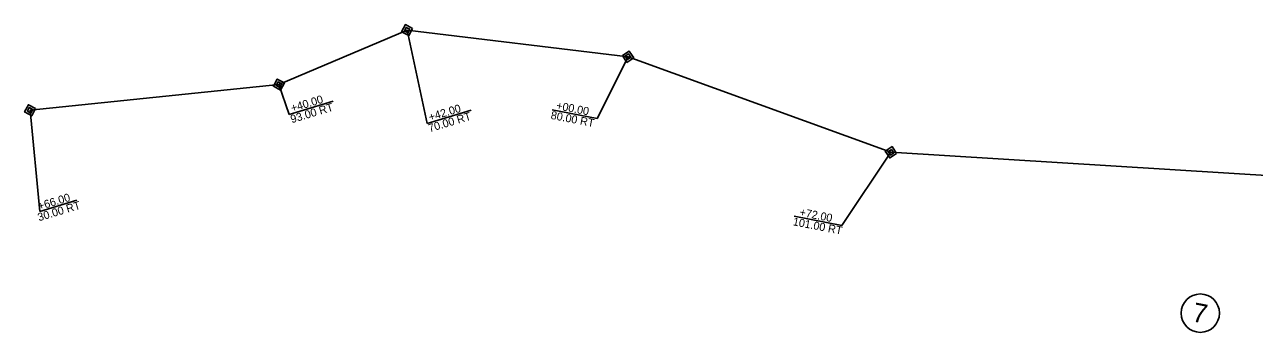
# Model space of a CAD drawing. Extents: x 1002576 to 1014655, y 551673 to 557994.
# Drawn here: x 1012562 to 1013330, y 552093 to 552285 of the extents above; entities that cross this region are included whole.
import ezdxf

# ---------------------------------------------------------------- set-up
doc = ezdxf.new("R2010")
doc.units = 0
for name, color, linetype in [('Exist Hydro Stream or Body of Water', 7, 'Continuous'), ('Exist Other Culture Area Outline', 7, 'Continuous'), ('Exist Roads EOP Other', 7, 'Continuous'), ('Exist Structure Major Deck Tunnel Box Culvert', 7, 'Continuous'), ('Exist Utilities Power Pole CELL', 7, 'Continuous')]:
    doc.layers.add(name, color=color, linetype=linetype)

msp = doc.modelspace()

# ---------------------------------------------------------------- linework, layer by layer
at = {"layer": 'Exist Hydro Stream or Body of Water'}
for p, q in [((1012800.68, 552281.9), (1012800.68, 552281.9)), ((1012938.71, 552265.3), (1012938.71, 552265.3)), ((1012720.6, 552247.86), (1012720.6, 552247.86)), ((1012565.11, 552231.82), (1012565.11, 552231.82)), ((1013102.95, 552205.62), (1013102.95, 552205.62))]:
    msp.add_line(p, q, dxfattribs=at)
at = {"layer": 'Exist Other Culture Area Outline'}
for p, q in [((1012720.6, 552247.86), (1012800.68, 552281.9)), ((1012800.68, 552281.9), (1012938.71, 552265.3)), ((1012938.71, 552265.3), (1013102.95, 552205.62)), ((1012565.11, 552231.82), (1012720.6, 552247.86)), ((1013102.95, 552205.62), (1013628.1, 552173.01))]:
    msp.add_line(p, q, dxfattribs=at)
at = {"layer": 'Exist Roads EOP Other'}
for p, q in [((1012754.47, 552237.6), (1012726.99, 552229.29)), ((1012840.58, 552231.94), (1012813.1, 552223.63)), ((1012919.42, 552226.73), (1012891.24, 552232.2)), ((1012594.27, 552175.66), (1012571.25, 552168.69)), ((1013072.22, 552159.99), (1013042.51, 552165.75))]:
    msp.add_line(p, q, dxfattribs=at)
for points in [[(1012813.1, 552223.63), (1012800.68, 552281.9)], [(1012919.42, 552226.73), (1012938.71, 552265.3)], [(1012726.99, 552229.29), (1012720.6, 552247.86)], [(1012571.25, 552168.69), (1012565.11, 552231.82)], [(1013072.22, 552159.99), (1013102.95, 552205.62)]]:
    msp.add_lwpolyline(points, dxfattribs=at)
at = {"layer": 'Exist Structure Major Deck Tunnel Box Culvert'}
for points in [[(1012804.12, 552282.94), (1012801.72, 552278.45), (1012797.23, 552280.86), (1012799.63, 552285.34)], [(1012802.4, 552282.42), (1012801.2, 552280.18), (1012798.95, 552281.38), (1012800.15, 552283.62)], [(1012942.24, 552264.61), (1012938.02, 552261.77), (1012935.17, 552265.99), (1012939.39, 552268.83)], [(1012940.47, 552264.96), (1012938.36, 552263.53), (1012936.94, 552265.64), (1012939.05, 552267.07)], [(1012724.04, 552248.9), (1012721.64, 552244.42), (1012717.15, 552246.82), (1012719.56, 552251.31)], [(1012722.32, 552248.38), (1012721.12, 552246.14), (1012718.88, 552247.34), (1012720.08, 552249.59)], [(1012568.56, 552232.86), (1012566.15, 552228.37), (1012561.67, 552230.78), (1012564.07, 552235.26)], [(1012566.83, 552232.34), (1012565.63, 552230.09), (1012563.39, 552231.3), (1012564.59, 552233.54)], [(1013106.48, 552204.94), (1013102.26, 552202.09), (1013099.41, 552206.31), (1013103.63, 552209.16)], [(1013104.71, 552205.28), (1013102.6, 552203.85), (1013101.18, 552205.96), (1013103.29, 552207.39)]]:
    msp.add_lwpolyline(points, close=True, dxfattribs=at)
at = {"layer": 'Exist Utilities Power Pole CELL'}
msp.add_line((1013296.23, 552105.14), (1013296.23, 552105.14), dxfattribs=at)
msp.add_circle((1013296.23, 552105.14), 12, dxfattribs=at)

# ---------------------------------------------------------------- texts
at = {"layer": 'Exist Roads EOP Other'}
for s, rotation, p in [('93.00 RT', 16.83036, (1012728.64, 552223.75)), ('+40.00', 16.83036, (1012728.86, 552230.66)), ('+42.00', 16.83036, (1012814.97, 552225.01)), ('+00.00', 349.01724, (1012893.53, 552232.55)), ('70.00 RT', 16.83036, (1012814.76, 552218.09)), ('80.00 RT', 349.01724, (1012890.12, 552226.54)), ('30.00 RT', 16.83036, (1012570.68, 552162.48)), ('+66.00', 16.83036, (1012570.89, 552169.39)), ('+72.00', 349.01724, (1013045.57, 552165.95)), ('101.00 RT', 349.01724, (1013041.39, 552160.09))]:
    msp.add_text(s, height=5, rotation=rotation, dxfattribs=at).set_placement(p)
at = {"layer": 'Exist Utilities Power Pole CELL'}
msp.add_text('7', height=12, rotation=349.01724, dxfattribs=at).set_placement((1013290.59, 552100.12))

doc.saveas('drawing.dxf')
